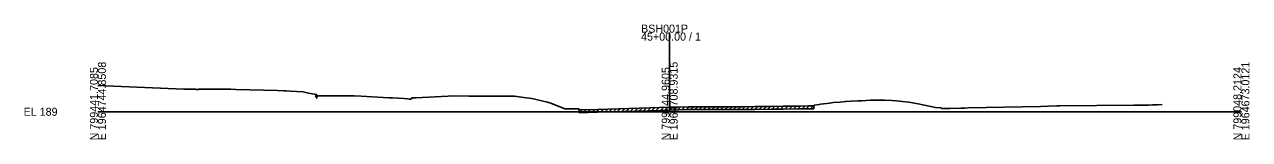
# Model space of a CAD drawing. Extents: x -26 to 1403, y -10 to 19587.
# Drawn here: x 974.3 to 1402.8, y 8990.3 to 9030.5 of the extents above; entities that cross this region are included whole.
import ezdxf

# ---------------------------------------------------------------- set-up
doc = ezdxf.new("R2010")
doc.units = 0
for name, color, linetype in [('Default', 7, 'Continuous'), ('RD_GPK_XS_Cell', 7, 'Continuous'), ('RD_XS_ExGround', 7, 'Continuous'), ('RD_XS_ExPaveRet', 7, 'Continuous'), ('RD_XS_TX_Elev_EX', 7, 'Continuous')]:
    doc.layers.add(name, color=color, linetype=linetype)

msp = doc.modelspace()

# ---------------------------------------------------------------- linework, layer by layer
at = {"layer": 'RD_GPK_XS_Cell'}
for p, q in [((1200, 9000), (1200, 9027.66)), ((1000, 9000), (1200, 9000)), ((1200, 9000), (1400, 9000))]:
    msp.add_line(p, q, dxfattribs=at)
at = {"layer": 'RD_XS_ExGround'}
msp.add_lwpolyline([(1000, 9009.22), (1030.05, 9007.89), (1034.17, 9007.92), (1035, 9007.7), (1035.01, 9007.89), (1036.02, 9007.94), (1044.66, 9007.87), (1046.46, 9007.85), (1048.24, 9007.83), (1062.76, 9007.43), (1065.07, 9007.37), (1065.69, 9007.36), (1067.39, 9007.22), (1071.83, 9006.93), (1073.7, 9006.55), (1076.45, 9006.07), (1076.55, 9005.62), (1085.8, 9005.56), (1088.64, 9005.52), (1089.62, 9005.52), (1092.11, 9005.47), (1101.73, 9004.92), (1103.07, 9004.85), (1104.97, 9004.72), (1107.16, 9004.59), (1108.31, 9004.47), (1108.86, 9004.44), (1109.57, 9004.39), (1109.8, 9004.82), (1111.21, 9004.88), (1124.78, 9005.51), (1129.72, 9005.43), (1141.41, 9005.46), (1144.15, 9005.45), (1145.72, 9005.42), (1148.97, 9004.94), (1151.81, 9004.61), (1157.3, 9003.33), (1157.65, 9003.25), (1158.38, 9002.98), (1162.77, 9001.29), (1163.28, 9001.06), (1165.28, 9001.06), (1168.21, 9000.98), (1168.31, 9000.63), (1174.7, 9000.83), (1193.08, 9001.38), (1200, 9001.56), (1206.61, 9001.75), (1225.39, 9001.76), (1229.81, 9001.81), (1235.5, 9001.88), (1239.7, 9001.93), (1245.52, 9001.98), (1248.57, 9002.04), (1250.39, 9002.05), (1250.58, 9002.3), (1252.31, 9002.55), (1252.78, 9002.63), (1256.08, 9003.03), (1257.2, 9003.18), (1259.64, 9003.38), (1261.36, 9003.59), (1261.71, 9003.61), (1263.45, 9003.68), (1265.79, 9003.82), (1267.24, 9003.85), (1270.11, 9004.03), (1271.32, 9004.02), (1273.94, 9004.05), (1275.23, 9004), (1277.71, 9003.91), (1279.36, 9003.79), (1281.4, 9003.56), (1283.64, 9003.3), (1286.88, 9002.82), (1292.97, 9001.44), (1294.94, 9001.4), (1295.05, 9001.16), (1296.86, 9001.14), (1298.04, 9001.14), (1301.91, 9001.29), (1303.3, 9001.3), (1304.37, 9001.32), (1329.74, 9001.89), (1335.49, 9002.02), (1336.35, 9002.05), (1362.32, 9002.26), (1363.15, 9002.32), (1364.19, 9002.3), (1365.35, 9002.34), (1366.22, 9002.34), (1367.52, 9002.36), (1368.93, 9002.44), (1370.14, 9002.45), (1370.82, 9002.46), (1372.29, 9002.48)], dxfattribs=at)
at = {"layer": 'RD_XS_ExPaveRet'}
for p, q in [((1076.25, 9005.1), (1076.25, 9006.1)), ((1076.25, 9005.1), (1076.45, 9005.07)), ((1076.45, 9005.07), (1076.55, 9004.62)), ((1076.55, 9005.62), (1076.55, 9004.62)), ((1168.31, 8999.63), (1169.34, 9000.66)), ((1168.31, 8999.63), (1168.31, 9000.63)), ((1168.31, 8999.63), (1174.7, 8999.83)), ((1169.81, 8999.67), (1170.84, 9000.71)), ((1171.31, 8999.72), (1172.34, 9000.75)), ((1172.81, 8999.77), (1173.84, 9000.8)), ((1174.31, 8999.82), (1175.34, 9000.85)), ((1174.7, 8999.83), (1193.08, 9000.38)), ((1175.81, 8999.86), (1176.84, 9000.89)), ((1177.31, 8999.91), (1178.34, 9000.94)), ((1178.81, 8999.95), (1179.84, 9000.98)), ((1180.31, 9000), (1181.34, 9001.03)), ((1181.81, 9000.04), (1182.84, 9001.08)), ((1183.31, 9000.09), (1184.34, 9001.12)), ((1184.81, 9000.13), (1185.84, 9001.17)), ((1186.31, 9000.18), (1187.34, 9001.21)), ((1187.81, 9000.22), (1188.84, 9001.26)), ((1189.31, 9000.27), (1190.34, 9001.3)), ((1190.81, 9000.32), (1191.84, 9001.35)), ((1192.31, 9000.36), (1193.34, 9001.39)), ((1193.08, 9000.38), (1200, 9000.56)), ((1193.81, 9000.4), (1194.83, 9001.43)), ((1195.31, 9000.44), (1196.33, 9001.47)), ((1196.81, 9000.48), (1197.83, 9001.51)), ((1198.31, 9000.52), (1199.33, 9001.54)), ((1199.81, 9000.56), (1200.84, 9001.58)), ((1200, 9000.56), (1206.61, 9000.75)), ((1201.31, 9000.6), (1202.34, 9001.63)), ((1202.81, 9000.64), (1203.84, 9001.67)), ((1204.31, 9000.68), (1205.34, 9001.71)), ((1205.81, 9000.73), (1206.83, 9001.75)), ((1206.61, 9000.75), (1225.39, 9000.76)), ((1207.31, 9000.75), (1208.31, 9001.75)), ((1208.81, 9000.75), (1209.81, 9001.75)), ((1210.31, 9000.75), (1211.31, 9001.75)), ((1211.81, 9000.75), (1212.81, 9001.75)), ((1213.31, 9000.75), (1214.31, 9001.75)), ((1214.81, 9000.75), (1215.81, 9001.75)), ((1216.31, 9000.75), (1217.31, 9001.75)), ((1217.81, 9000.75), (1218.81, 9001.75)), ((1219.31, 9000.75), (1220.31, 9001.75)), ((1220.81, 9000.75), (1221.81, 9001.75)), ((1222.31, 9000.76), (1223.31, 9001.76)), ((1223.81, 9000.76), (1224.81, 9001.76)), ((1225.31, 9000.76), (1226.32, 9001.77)), ((1225.39, 9000.76), (1229.81, 9000.81)), ((1226.81, 9000.77), (1227.82, 9001.79)), ((1228.31, 9000.79), (1229.32, 9001.8)), ((1229.81, 9000.81), (1230.82, 9001.82)), ((1229.81, 9000.81), (1235.5, 9000.88)), ((1231.31, 9000.83), (1232.32, 9001.84)), ((1232.81, 9000.85), (1233.82, 9001.86)), ((1234.31, 9000.86), (1235.32, 9001.88)), ((1235.5, 9000.88), (1239.7, 9000.93)), ((1235.81, 9000.88), (1236.82, 9001.9)), ((1237.31, 9000.9), (1238.32, 9001.91)), ((1238.81, 9000.92), (1239.82, 9001.93)), ((1239.7, 9000.93), (1245.52, 9000.98)), ((1240.31, 9000.93), (1241.32, 9001.94)), ((1241.81, 9000.95), (1242.82, 9001.95)), ((1243.31, 9000.96), (1244.32, 9001.97)), ((1244.81, 9000.97), (1245.82, 9001.98)), ((1245.52, 9000.98), (1248.57, 9001.04)), ((1246.31, 9000.99), (1247.33, 9002.01)), ((1247.81, 9001.02), (1248.83, 9002.04)), ((1248.57, 9001.04), (1250.39, 9001.05)), ((1249.31, 9001.04), (1250.31, 9002.05)), ((1250.39, 9002.05), (1250.39, 9001.05))]:
    msp.add_line(p, q, dxfattribs=at)

# ---------------------------------------------------------------- texts
at = {"layer": 'Default'}
msp.add_text('-', height=0.0001, dxfattribs=at).set_placement((1000, 9000))
at = {"layer": 'RD_GPK_XS_Cell'}
for s, p in [('BSH001P', (1190, 9027.66)), ('45+00.00 / 1', (1190, 9024.86)), ('EL 189', (974, 8998.6))]:
    msp.add_text(s, height=2.8, dxfattribs=at).set_placement(p)
for s, p in [('E 1964744.8508', (1002.8, 8990)), ('E 1964708.9315', (1202.8, 8990)), ('E 1964673.0121', (1402.8, 8990)), ('N 799441.7085', (1000, 8990)), ('N 799244.9605', (1200, 8990)), ('N 799048.2124', (1400, 8990))]:
    msp.add_text(s, height=2.8, rotation=90, dxfattribs=at).set_placement(p)
at = {"layer": 'RD_XS_TX_Elev_EX'}
msp.add_text('190.56', height=1, dxfattribs=at).set_placement((1197.95, 8999.06))

doc.saveas('drawing.dxf')
